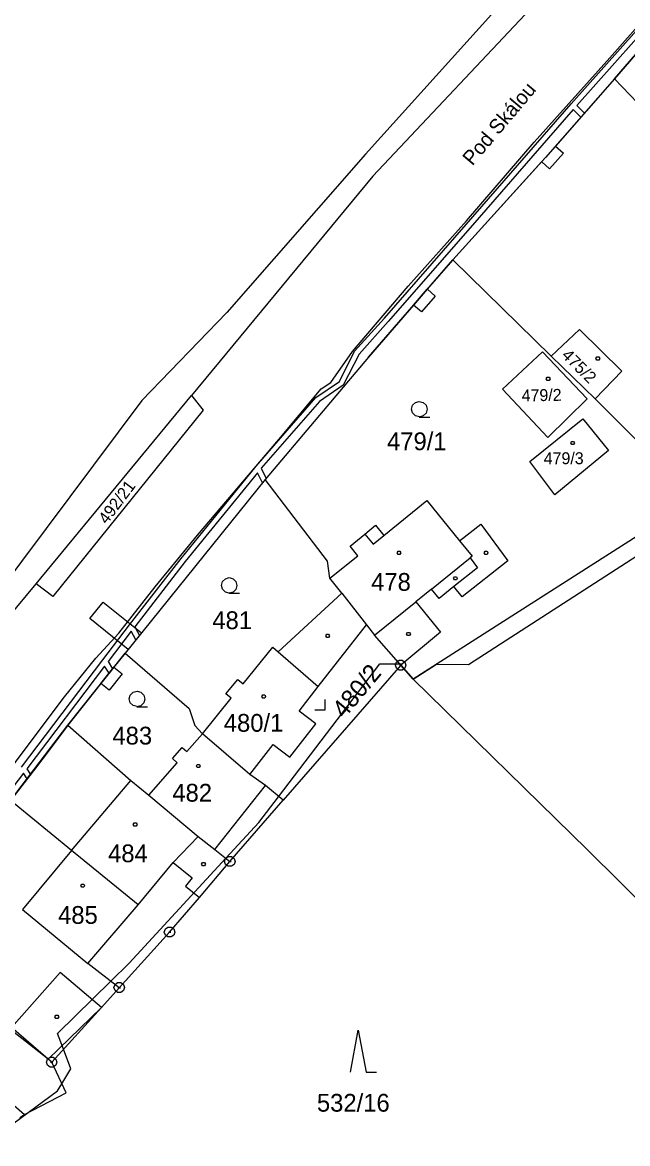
# Model space of a CAD drawing. Extents: x -759699 to -757730, y -1172308 to -1170857.
# Drawn here: x -759493.5 to -759435.7, y -1171818.3 to -1171711.2 of the extents above; entities that cross this region are included whole.
import ezdxf

# ---------------------------------------------------------------- set-up
doc = ezdxf.new("R2010")
doc.units = 0
for name, color, linetype in [('Vrstva 1', 7, 'Continuous'), ('Vrstva 11', 7, 'Continuous'), ('Vrstva 12', 7, 'Continuous'), ('Vrstva 13', 7, 'Continuous'), ('Vrstva 2', 7, 'Continuous'), ('Vrstva 3', 7, 'Continuous'), ('Vrstva 4', 7, 'Continuous'), ('Vrstva 5', 7, 'Continuous'), ('Vrstva 7', 7, 'Continuous'), ('Vrstva 8', 7, 'Continuous')]:
    doc.layers.add(name, color=color, linetype=linetype)

msp = doc.modelspace()

# ---------------------------------------------------------------- linework, layer by layer
at = {"layer": 'Vrstva 1'}
for p, q in [((-759411.06, -1171673.74), (-759460.06, -1171725.87)), ((-759436.98, -1171716.58), (-759431.38, -1171710.06)), ((-759436.98, -1171716.58), (-759443.56, -1171724.07)), ((-759426.3, -1171727.72), (-759436.98, -1171716.58)), ((-759452.43, -1171733.85), (-759443.56, -1171724.07)), ((-759460.06, -1171725.87), (-759477.37, -1171746.83)), ((-759460.46, -1171743.16), (-759452.43, -1171733.85)), ((-759452.43, -1171733.85), (-759443.02, -1171743.06)), ((-759443.02, -1171743.06), (-759440.32, -1171740.54)), ((-759440.32, -1171740.54), (-759436.26, -1171744.52)), ((-759447.66, -1171746.24), (-759443.86, -1171742.67)), ((-759443.86, -1171742.67), (-759439.57, -1171747.14)), ((-759438.83, -1171747.15), (-759443.02, -1171743.06)), ((-759460.46, -1171743.16), (-759470.34, -1171754.86)), ((-759436.26, -1171744.52), (-759438.83, -1171747.15)), ((-759443.33, -1171750.84), (-759447.66, -1171746.24)), ((-759492.23, -1171764.82), (-759477.37, -1171746.83)), ((-759477.37, -1171746.83), (-759476.27, -1171748.22)), ((-759439.57, -1171747.14), (-759443.33, -1171750.84)), ((-759438.83, -1171747.15), (-759429.27, -1171756.73)), ((-759476.27, -1171748.22), (-759490.63, -1171766.05)), ((-759445.05, -1171753.14), (-759439.99, -1171749.05)), ((-759439.99, -1171749.05), (-759437.54, -1171752.08)), ((-759437.54, -1171752.08), (-759442.66, -1171756.31)), ((-759442.66, -1171756.31), (-759445.05, -1171753.14)), ((-759470.34, -1171754.86), (-759483.72, -1171771.46)), ((-759464.38, -1171762.65), (-759470.34, -1171754.86)), ((-759459.01, -1171760.2), (-759454.91, -1171756.88)), ((-759429.27, -1171756.73), (-759456.21, -1171773.94)), ((-759454.91, -1171756.88), (-759451.77, -1171760.72)), ((-759451.77, -1171760.72), (-759449.75, -1171759.13)), ((-759449.75, -1171759.13), (-759447.16, -1171762.64)), ((-759462.24, -1171761.24), (-759460.82, -1171760.07)), ((-759460.82, -1171760.07), (-759459.79, -1171759.24)), ((-759459.79, -1171759.24), (-759459.01, -1171760.2)), ((-759461.5, -1171762.16), (-759462.24, -1171761.24)), ((-759464.16, -1171764.29), (-759461.5, -1171762.16)), ((-759464.16, -1171764.29), (-759464.38, -1171762.65)), ((-759447.16, -1171762.64), (-759451.54, -1171766.07)), ((-759463.03, -1171765.74), (-759464.16, -1171764.29)), ((-759506.59, -1171782.21), (-759492.23, -1171764.82)), ((-759490.63, -1171766.05), (-759492.23, -1171764.82)), ((-759454.45, -1171765.33), (-759455.94, -1171766.54)), ((-759453.73, -1171766.22), (-759454.45, -1171765.33)), ((-759452.32, -1171765.09), (-759453.73, -1171766.22)), ((-759451.54, -1171766.07), (-759452.32, -1171765.09)), ((-759469.12, -1171771.32), (-759463.03, -1171765.74)), ((-759463.03, -1171765.74), (-759460.68, -1171768.74)), ((-759455.94, -1171766.54), (-759453.59, -1171769.46)), ((-759465.28, -1171774.66), (-759460.68, -1171768.74)), ((-759460.68, -1171768.74), (-759459.9, -1171769.74)), ((-759457.4, -1171772.61), (-759459.9, -1171769.74)), ((-759453.59, -1171769.46), (-759457.4, -1171772.61)), ((-759472.45, -1171774.38), (-759469.61, -1171770.89)), ((-759469.61, -1171770.89), (-759469.12, -1171771.32)), ((-759489.2, -1171778.33), (-759483.72, -1171771.46)), ((-759483.72, -1171771.46), (-759477.62, -1171776.75)), ((-759457.4, -1171772.61), (-759468.63, -1171785.52)), ((-759456.21, -1171773.94), (-759457.4, -1171772.61)), ((-759474.1, -1171775.36), (-759472.97, -1171773.97)), ((-759472.97, -1171773.97), (-759472.45, -1171774.38)), ((-759456.21, -1171773.94), (-759439.54, -1171790.25)), ((-759467.09, -1171776.99), (-759465.28, -1171774.66)), ((-759476.34, -1171779.16), (-759473.58, -1171775.77)), ((-759473.58, -1171775.77), (-759474.1, -1171775.36)), ((-759477.62, -1171776.75), (-759477.05, -1171778.38)), ((-759465.51, -1171778.21), (-759467.09, -1171776.99)), ((-759494.67, -1171785.55), (-759489.2, -1171778.33)), ((-759489.2, -1171778.33), (-759483.17, -1171783.63)), ((-759477.05, -1171778.38), (-759476.34, -1171779.16)), ((-759467.99, -1171781.41), (-759465.51, -1171778.21)), ((-759477.82, -1171780.86), (-759476.34, -1171779.16)), ((-759471.81, -1171783.07), (-759476.34, -1171779.16)), ((-759479.21, -1171781.53), (-759478.28, -1171780.46)), ((-759478.28, -1171780.46), (-759477.82, -1171780.86)), ((-759471.81, -1171783.07), (-759469.57, -1171780.19)), ((-759469.57, -1171780.19), (-759467.99, -1171781.41)), ((-759478.75, -1171781.93), (-759479.21, -1171781.53)), ((-759481.47, -1171785.04), (-759478.75, -1171781.93)), ((-759483.17, -1171783.63), (-759481.47, -1171785.04)), ((-759470.31, -1171784.12), (-759471.81, -1171783.07)), ((-759468.63, -1171785.52), (-759470.31, -1171784.12)), ((-759488.86, -1171790.32), (-759494.67, -1171785.55)), ((-759481.47, -1171785.04), (-759476.76, -1171788.98)), ((-759473.71, -1171791.37), (-759468.63, -1171785.52)), ((-759476.76, -1171788.98), (-759475.17, -1171790.21)), ((-759475.17, -1171790.21), (-759473.71, -1171791.37)), ((-759439.54, -1171790.25), (-759416.59, -1171813.09)), ((-759482.48, -1171795.51), (-759488.86, -1171790.32)), ((-759476.63, -1171794.8), (-759473.71, -1171791.37)), ((-759487.29, -1171801.11), (-759482.48, -1171795.51)), ((-759479.47, -1171798.12), (-759476.63, -1171794.8)), ((-759479.47, -1171798.12), (-759484.28, -1171803.43)), ((-759484.28, -1171803.43), (-759487.29, -1171801.11)), ((-759485.98, -1171805.31), (-759484.28, -1171803.43)), ((-759490.74, -1171810.56), (-759485.98, -1171805.31)), ((-759491.08, -1171810.27), (-759494.57, -1171807.25)), ((-759490.74, -1171810.56), (-759491.08, -1171810.27)), ((-759489.36, -1171813.49), (-759490.74, -1171810.56)), ((-759493.35, -1171815.54), (-759489.36, -1171813.49)), ((-759493.78, -1171815.83), (-759493.35, -1171815.54))]:
    msp.add_line(p, q, dxfattribs=at)
at = {"layer": 'Vrstva 11'}
for p, q in [((-759424.03, -1171682.98), (-759460.77, -1171723.76)), ((-759460.77, -1171723.76), (-759474.02, -1171738.9)), ((-759474.02, -1171738.9), (-759482.13, -1171747.3)), ((-759482.13, -1171747.3), (-759506.1, -1171779.29)), ((-759450.91, -1171772.55), (-759429.61, -1171758.75)), ((-759469.08, -1171785.18), (-759459.39, -1171772.48)), ((-759459.39, -1171772.48), (-759457.5, -1171772.49)), ((-759457.5, -1171772.49), (-759457.26, -1171772.49)), ((-759457.26, -1171772.49), (-759457.4, -1171772.61)), ((-759457.4, -1171772.61), (-759456.21, -1171773.94)), ((-759456.21, -1171773.94), (-759453.99, -1171772.52)), ((-759453.99, -1171772.52), (-759450.91, -1171772.55)), ((-759470.95, -1171787.63), (-759469.08, -1171785.18)), ((-759474.11, -1171791.06), (-759470.95, -1171787.63)), ((-759483.34, -1171801.08), (-759474.11, -1171791.06)), ((-759485.09, -1171802.81), (-759483.34, -1171801.08)), ((-759490.17, -1171807.8), (-759485.09, -1171802.81)), ((-759489.61, -1171809.31), (-759490.17, -1171807.8)), ((-759488.92, -1171811.2), (-759489.61, -1171809.31)), ((-759489.78, -1171812.61), (-759488.92, -1171811.2)), ((-759490.2, -1171813.3), (-759489.78, -1171812.61)), ((-759492.98, -1171815.35), (-759490.2, -1171813.3)), ((-759497.02, -1171818.33), (-759492.98, -1171815.35))]:
    msp.add_line(p, q, dxfattribs=at)
at = {"layer": 'Vrstva 12'}
for p, q in [((-759443.02, -1171743.06), (-759440.32, -1171740.54)), ((-759440.32, -1171740.54), (-759436.26, -1171744.52)), ((-759447.66, -1171746.24), (-759443.86, -1171742.67)), ((-759443.86, -1171742.67), (-759439.57, -1171747.14)), ((-759438.83, -1171747.15), (-759443.02, -1171743.06)), ((-759436.26, -1171744.52), (-759438.83, -1171747.15)), ((-759443.33, -1171750.84), (-759447.66, -1171746.24)), ((-759439.57, -1171747.14), (-759443.33, -1171750.84)), ((-759445.05, -1171753.14), (-759439.99, -1171749.05)), ((-759439.99, -1171749.05), (-759437.54, -1171752.08)), ((-759437.54, -1171752.08), (-759442.66, -1171756.31)), ((-759442.66, -1171756.31), (-759445.05, -1171753.14)), ((-759459.01, -1171760.2), (-759454.91, -1171756.88)), ((-759454.91, -1171756.88), (-759451.77, -1171760.72)), ((-759462.24, -1171761.24), (-759460.82, -1171760.07)), ((-759460.82, -1171760.07), (-759460.04, -1171761.03)), ((-759460.04, -1171761.03), (-759459.01, -1171760.2)), ((-759461.5, -1171762.16), (-759462.24, -1171761.24)), ((-759451.77, -1171760.72), (-759450.57, -1171762.19)), ((-759464.16, -1171764.29), (-759461.5, -1171762.16)), ((-759454.45, -1171765.33), (-759450.77, -1171762.35)), ((-759450.57, -1171762.19), (-759450.77, -1171762.35)), ((-759463.03, -1171765.74), (-759464.16, -1171764.29)), ((-759454.45, -1171765.33), (-759455.94, -1171766.54)), ((-759463.03, -1171765.74), (-759460.68, -1171768.74)), ((-759459.9, -1171769.74), (-759455.94, -1171766.54)), ((-759460.68, -1171768.74), (-759459.9, -1171769.74)), ((-759472.45, -1171774.38), (-759469.61, -1171770.89)), ((-759469.61, -1171770.89), (-759469.12, -1171771.32)), ((-759469.12, -1171771.32), (-759465.28, -1171774.66)), ((-759474.1, -1171775.36), (-759472.97, -1171773.97)), ((-759472.97, -1171773.97), (-759472.45, -1171774.38)), ((-759467.09, -1171776.99), (-759465.28, -1171774.66)), ((-759476.34, -1171779.16), (-759473.58, -1171775.77)), ((-759473.58, -1171775.77), (-759474.1, -1171775.36)), ((-759465.51, -1171778.21), (-759467.09, -1171776.99)), ((-759467.99, -1171781.41), (-759465.51, -1171778.21)), ((-759477.82, -1171780.86), (-759476.34, -1171779.16)), ((-759471.81, -1171783.07), (-759476.34, -1171779.16)), ((-759471.81, -1171783.07), (-759476.34, -1171779.16)), ((-759479.21, -1171781.53), (-759478.28, -1171780.46)), ((-759478.28, -1171780.46), (-759477.82, -1171780.86)), ((-759471.81, -1171783.07), (-759469.57, -1171780.19)), ((-759469.57, -1171780.19), (-759467.99, -1171781.41)), ((-759478.75, -1171781.93), (-759479.21, -1171781.53)), ((-759481.47, -1171785.04), (-759478.75, -1171781.93)), ((-759488.86, -1171790.32), (-759483.17, -1171783.63)), ((-759483.17, -1171783.63), (-759481.47, -1171785.04)), ((-759470.31, -1171784.12), (-759471.81, -1171783.07)), ((-759475.17, -1171790.21), (-759470.31, -1171784.12)), ((-759481.47, -1171785.04), (-759476.76, -1171788.98)), ((-759481.47, -1171785.04), (-759476.76, -1171788.98)), ((-759479.15, -1171791.45), (-759476.76, -1171788.98)), ((-759476.76, -1171788.98), (-759475.17, -1171790.21)), ((-759488.86, -1171790.32), (-759493.53, -1171795.95)), ((-759482.48, -1171795.51), (-759488.86, -1171790.32)), ((-759482.48, -1171795.51), (-759488.86, -1171790.32)), ((-759482.48, -1171795.51), (-759479.15, -1171791.45)), ((-759487.29, -1171801.11), (-759482.48, -1171795.51)), ((-759493.53, -1171795.95), (-759487.29, -1171801.11))]:
    msp.add_line(p, q, dxfattribs=at)
at = {"layer": 'Vrstva 13'}
for p, q in [((-759437.42, -1171714.55), (-759429.1, -1171705.11)), ((-759441.11, -1171718.97), (-759432.23, -1171708.97)), ((-759432.02, -1171709.49), (-759440.58, -1171719.13)), ((-759431.38, -1171710.06), (-759436.98, -1171716.58)), ((-759444.65, -1171722.63), (-759437.42, -1171714.55)), ((-759436.98, -1171716.58), (-759442.62, -1171723)), ((-759451.13, -1171730.48), (-759441.11, -1171718.97)), ((-759440.91, -1171719.5), (-759450.76, -1171730.8)), ((-759440.19, -1171720.23), (-759440.91, -1171719.5)), ((-759440.58, -1171719.13), (-759439.85, -1171719.85)), ((-759439.85, -1171719.85), (-759440.19, -1171720.23)), ((-759451.1, -1171730.14), (-759444.65, -1171722.63)), ((-759442.62, -1171723), (-759443.56, -1171724.07)), ((-759443.56, -1171724.07), (-759442.62, -1171723)), ((-759441.86, -1171723.67), (-759443.18, -1171725.17)), ((-759442.62, -1171723), (-759442.6, -1171723.01)), ((-759442.6, -1171723.01), (-759441.86, -1171723.67)), ((-759443.94, -1171724.49), (-759452.43, -1171733.85)), ((-759443.56, -1171724.07), (-759443.94, -1171724.49)), ((-759443.94, -1171724.49), (-759443.56, -1171724.07)), ((-759443.93, -1171724.5), (-759443.94, -1171724.49)), ((-759443.18, -1171725.17), (-759443.93, -1171724.5)), ((-759456.67, -1171736.39), (-759451.1, -1171730.14)), ((-759458.95, -1171739.43), (-759451.13, -1171730.48)), ((-759450.76, -1171730.8), (-759458.58, -1171739.76)), ((-759452.43, -1171733.85), (-759454.86, -1171736.67)), ((-759462, -1171742.64), (-759456.67, -1171736.39)), ((-759454.86, -1171736.67), (-759456.16, -1171738.19)), ((-759456.16, -1171738.19), (-759454.86, -1171736.67)), ((-759454.86, -1171736.67), (-759454.85, -1171736.68)), ((-759454.85, -1171736.68), (-759454.1, -1171737.33)), ((-759454.1, -1171737.33), (-759455.41, -1171738.85)), ((-759456.16, -1171738.19), (-759460.46, -1171743.16)), ((-759455.41, -1171738.85), (-759456.16, -1171738.19)), ((-759461.8, -1171742.6), (-759458.95, -1171739.43)), ((-759458.58, -1171739.76), (-759461.38, -1171742.88)), ((-759464.06, -1171745.6), (-759462, -1171742.64)), ((-759463.26, -1171745.5), (-759461.8, -1171742.6)), ((-759461.38, -1171742.88), (-759462.88, -1171745.84)), ((-759460.46, -1171743.16), (-759470.34, -1171754.86)), ((-759469.04, -1171751.04), (-759465, -1171746.21)), ((-759465.49, -1171747.01), (-759463.26, -1171745.5)), ((-759462.88, -1171745.84), (-759465.15, -1171747.39)), ((-759465, -1171746.21), (-759464.06, -1171745.6)), ((-759471.21, -1171753.59), (-759465.49, -1171747.01)), ((-759465.15, -1171747.39), (-759470.72, -1171753.79)), ((-759476.82, -1171760.17), (-759469.04, -1171751.04)), ((-759472.59, -1171755.27), (-759471.21, -1171753.59)), ((-759470.72, -1171753.79), (-759470.25, -1171754.75)), ((-759470.34, -1171754.86), (-759483.72, -1171771.46)), ((-759471.07, -1171754.21), (-759472.2, -1171755.59)), ((-759470.6, -1171755.18), (-759471.07, -1171754.21)), ((-759470.34, -1171754.86), (-759470.6, -1171755.18)), ((-759470.25, -1171754.75), (-759470.34, -1171754.86)), ((-759478.38, -1171762.4), (-759472.59, -1171755.27)), ((-759472.2, -1171755.59), (-759477.99, -1171762.71)), ((-759480.87, -1171765.13), (-759476.82, -1171760.17)), ((-759483.3, -1171768.76), (-759478.38, -1171762.4)), ((-759477.99, -1171762.71), (-759482.8, -1171768.94)), ((-759484.33, -1171769.56), (-759480.87, -1171765.13)), ((-759487.09, -1171768.15), (-759485.82, -1171766.58)), ((-759485.82, -1171766.58), (-759482.16, -1171769.53)), ((-759483.43, -1171771.1), (-759487.09, -1171768.15)), ((-759485.86, -1171772.1), (-759483.3, -1171768.76)), ((-759486.52, -1171771.93), (-759484.33, -1171769.56)), ((-759483.14, -1171769.37), (-759485.36, -1171772.27)), ((-759482.16, -1171769.53), (-759483.43, -1171771.1)), ((-759482.71, -1171770.2), (-759483.14, -1171769.37)), ((-759482.8, -1171768.94), (-759482.36, -1171769.78)), ((-759482.36, -1171769.78), (-759482.71, -1171770.2)), ((-759489.53, -1171775.62), (-759486.52, -1171771.93)), ((-759483.72, -1171771.46), (-759484.79, -1171772.81)), ((-759493.63, -1171782.34), (-759485.86, -1171772.1)), ((-759485.68, -1171772.69), (-759493.12, -1171782.51)), ((-759484.79, -1171772.81), (-759486.03, -1171774.37)), ((-759486.03, -1171774.37), (-759484.79, -1171772.81)), ((-759485.25, -1171773.38), (-759485.68, -1171772.69)), ((-759485.36, -1171772.27), (-759484.92, -1171772.97)), ((-759484.92, -1171772.97), (-759485.25, -1171773.38)), ((-759484.79, -1171772.81), (-759484, -1171773.43)), ((-759484, -1171773.43), (-759485.25, -1171775)), ((-759486.03, -1171774.37), (-759489.2, -1171778.33)), ((-759485.25, -1171775), (-759486.03, -1171774.37)), ((-759493.18, -1171780.51), (-759489.53, -1171775.62)), ((-759489.2, -1171778.33), (-759491.09, -1171780.85)), ((-759497.62, -1171786.39), (-759493.18, -1171780.51)), ((-759491.09, -1171780.85), (-759492.3, -1171782.45)), ((-759492.3, -1171782.45), (-759494.67, -1171785.55)), ((-759493.12, -1171782.51), (-759492.77, -1171783.04)), ((-759493.44, -1171782.93), (-759495.37, -1171785.47)), ((-759493.09, -1171783.47), (-759493.44, -1171782.93)), ((-759492.77, -1171783.04), (-759493.09, -1171783.47))]:
    msp.add_line(p, q, dxfattribs=at)
at = {"layer": 'Vrstva 3'}
for points in [[(-759455.61, -1171748.87), (-759455.99, -1171748.77), (-759456.26, -1171748.5), (-759456.36, -1171748.13), (-759456.26, -1171747.76), (-759455.99, -1171747.49), (-759455.62, -1171747.39), (-759455.25, -1171747.49), (-759454.98, -1171747.76), (-759454.88, -1171748.14), (-759454.98, -1171748.52), (-759455.25, -1171748.79), (-759455.63, -1171748.89), (-759454.63, -1171748.89)], [(-759473.77, -1171765.72), (-759474.15, -1171765.62), (-759474.42, -1171765.35), (-759474.52, -1171764.98), (-759474.42, -1171764.61), (-759474.15, -1171764.34), (-759473.78, -1171764.24), (-759473.41, -1171764.34), (-759473.14, -1171764.61), (-759473.04, -1171764.99), (-759473.14, -1171765.37), (-759473.41, -1171765.64), (-759473.79, -1171765.74), (-759472.79, -1171765.74)], [(-759482.58, -1171776.57), (-759482.96, -1171776.47), (-759483.23, -1171776.2), (-759483.33, -1171775.83), (-759483.23, -1171775.46), (-759482.96, -1171775.19), (-759482.59, -1171775.09), (-759482.22, -1171775.19), (-759481.95, -1171775.46), (-759481.85, -1171775.84), (-759481.95, -1171776.22), (-759482.22, -1171776.49), (-759482.6, -1171776.59), (-759481.6, -1171776.59)], [(-759465.61, -1171776.88), (-759464.61, -1171776.88), (-759464.61, -1171775.88)], [(-759462.2, -1171811.5), (-759461.45, -1171807.5), (-759460.7, -1171811.5), (-759459.7, -1171811.5)]]:
    msp.add_lwpolyline(points, dxfattribs=at)
at = {"layer": 'Vrstva 4'}
for p, q in [((-759460.82, -1171760.07), (-759460.04, -1171761.03)), ((-759460.04, -1171761.03), (-759459.01, -1171760.2)), ((-759451.77, -1171760.72), (-759450.57, -1171762.19)), ((-759454.45, -1171765.33), (-759450.77, -1171762.35)), ((-759450.57, -1171762.19), (-759450.77, -1171762.35)), ((-759450.77, -1171762.35), (-759450.06, -1171763.29)), ((-759450.06, -1171763.29), (-759452.32, -1171765.09)), ((-759459.9, -1171769.74), (-759455.94, -1171766.54)), ((-759469.12, -1171771.32), (-759465.28, -1171774.66)), ((-759488.86, -1171790.32), (-759483.17, -1171783.63)), ((-759475.17, -1171790.21), (-759470.31, -1171784.12)), ((-759479.15, -1171791.45), (-759476.76, -1171788.98)), ((-759488.86, -1171790.32), (-759493.53, -1171795.95)), ((-759482.48, -1171795.51), (-759479.15, -1171791.45)), ((-759479.15, -1171791.45), (-759477.33, -1171792.93)), ((-759477.33, -1171792.93), (-759477.97, -1171793.72)), ((-759477.97, -1171793.72), (-759476.63, -1171794.8)), ((-759493.53, -1171795.95), (-759487.29, -1171801.11)), ((-759489.93, -1171801.99), (-759494.57, -1171807.25)), ((-759485.98, -1171805.31), (-759489.93, -1171801.99)), ((-759491.08, -1171810.27), (-759485.98, -1171805.31)), ((-759491.08, -1171810.27), (-759495.36, -1171806.9)), ((-759499.07, -1171810.57), (-759493.35, -1171815.54))]:
    msp.add_line(p, q, dxfattribs=at)
at = {"layer": 'Vrstva 5'}
for points in [[(-759438.48, -1171743.14), (-759438.39, -1171743.29), (-759438.48, -1171743.44), (-759438.66, -1171743.44), (-759438.75, -1171743.29), (-759438.66, -1171743.14)], [(-759443.22, -1171745.09), (-759443.13, -1171745.24), (-759443.22, -1171745.39), (-759443.4, -1171745.39), (-759443.49, -1171745.24), (-759443.4, -1171745.09)], [(-759440.88, -1171751.22), (-759440.79, -1171751.37), (-759440.88, -1171751.52), (-759441.06, -1171751.52), (-759441.15, -1171751.37), (-759441.06, -1171751.22)], [(-759457.47, -1171761.72), (-759457.38, -1171761.87), (-759457.47, -1171762.02), (-759457.65, -1171762.02), (-759457.74, -1171761.87), (-759457.65, -1171761.72)], [(-759449.15, -1171761.72), (-759449.06, -1171761.87), (-759449.15, -1171762.02), (-759449.33, -1171762.02), (-759449.42, -1171761.87), (-759449.33, -1171761.72)], [(-759452.08, -1171764.15), (-759451.99, -1171764.3), (-759452.08, -1171764.45), (-759452.26, -1171764.45), (-759452.35, -1171764.3), (-759452.26, -1171764.15)], [(-759464.29, -1171769.65), (-759464.2, -1171769.8), (-759464.29, -1171769.95), (-759464.47, -1171769.95), (-759464.56, -1171769.8), (-759464.47, -1171769.65)], [(-759456.56, -1171769.47), (-759456.47, -1171769.62), (-759456.56, -1171769.77), (-759456.74, -1171769.77), (-759456.83, -1171769.62), (-759456.74, -1171769.47)], [(-759470.39, -1171775.45), (-759470.3, -1171775.6), (-759470.39, -1171775.75), (-759470.57, -1171775.75), (-759470.66, -1171775.6), (-759470.57, -1171775.45)], [(-759476.65, -1171782.09), (-759476.56, -1171782.24), (-759476.65, -1171782.39), (-759476.83, -1171782.39), (-759476.92, -1171782.24), (-759476.83, -1171782.09)], [(-759482.68, -1171787.69), (-759482.59, -1171787.84), (-759482.68, -1171787.99), (-759482.86, -1171787.99), (-759482.95, -1171787.84), (-759482.86, -1171787.69)], [(-759476.15, -1171791.48), (-759476.06, -1171791.63), (-759476.15, -1171791.78), (-759476.33, -1171791.78), (-759476.42, -1171791.63), (-759476.33, -1171791.48)], [(-759487.68, -1171793.53), (-759487.59, -1171793.68), (-759487.68, -1171793.83), (-759487.86, -1171793.83), (-759487.95, -1171793.68), (-759487.86, -1171793.53)], [(-759490.16, -1171806.07), (-759490.07, -1171806.22), (-759490.16, -1171806.37), (-759490.34, -1171806.37), (-759490.43, -1171806.22), (-759490.34, -1171806.07)]]:
    msp.add_lwpolyline(points, close=True, dxfattribs=at)
at = {"layer": 'Vrstva 8'}
for p, q in [((-759457.52, -1171772.61), (-759457.28, -1171772.61)), ((-759473.83, -1171791.37), (-759473.59, -1171791.37)), ((-759479.59, -1171798.12), (-759479.35, -1171798.12)), ((-759484.4, -1171803.43), (-759484.16, -1171803.43)), ((-759490.86, -1171810.56), (-759490.62, -1171810.56))]:
    msp.add_line(p, q, dxfattribs=at)
for points in [[(-759457.25, -1171772.13), (-759457, -1171772.31), (-759456.9, -1171772.6), (-759457, -1171772.89), (-759457.25, -1171773.07), (-759457.56, -1171773.07), (-759457.81, -1171772.89), (-759457.91, -1171772.6), (-759457.81, -1171772.31), (-759457.56, -1171772.13)], [(-759473.56, -1171790.89), (-759473.31, -1171791.07), (-759473.21, -1171791.36), (-759473.31, -1171791.65), (-759473.56, -1171791.83), (-759473.87, -1171791.83), (-759474.12, -1171791.65), (-759474.22, -1171791.36), (-759474.12, -1171791.07), (-759473.87, -1171790.89)], [(-759479.32, -1171797.64), (-759479.07, -1171797.82), (-759478.97, -1171798.11), (-759479.07, -1171798.4), (-759479.32, -1171798.58), (-759479.63, -1171798.58), (-759479.88, -1171798.4), (-759479.98, -1171798.11), (-759479.88, -1171797.82), (-759479.63, -1171797.64)], [(-759484.13, -1171802.95), (-759483.88, -1171803.13), (-759483.78, -1171803.42), (-759483.88, -1171803.71), (-759484.13, -1171803.89), (-759484.44, -1171803.89), (-759484.69, -1171803.71), (-759484.79, -1171803.42), (-759484.69, -1171803.13), (-759484.44, -1171802.95)], [(-759490.59, -1171810.08), (-759490.34, -1171810.26), (-759490.24, -1171810.55), (-759490.34, -1171810.84), (-759490.59, -1171811.02), (-759490.9, -1171811.02), (-759491.15, -1171810.84), (-759491.25, -1171810.55), (-759491.15, -1171810.26), (-759490.9, -1171810.08)]]:
    msp.add_lwpolyline(points, close=True, dxfattribs=at)

# ---------------------------------------------------------------- texts
at = {"layer": 'Vrstva 2'}
for s, height, rotation, p in [('475/2', 1.14, 315.01219, (-759442.096, -1171743.074)), ('479/2', 1.14, 0.91673, (-759445.834, -1171747.397)), ('492/21', 1.14, 52.9986, (-759485.473, -1171759.21)), ('480/2', 1.7, 50.1911, (-759462.789, -1171777.785))]:
    msp.add_text(s, height=height, rotation=rotation, dxfattribs=at).set_placement(p)
for s, height, p in [('479/1', 1.7, (-759458.705, -1171752.06)), ('479/3', 1.14, (-759443.734, -1171753.4)), ('478', 1.7, (-759460.224, -1171765.5)), ('481', 1.7, (-759475.393, -1171769.16)), ('480/1', 1.7, (-759474.299, -1171778.97)), ('483', 1.7, (-759484.938, -1171780.19)), ('482', 1.7, (-759479.215, -1171785.65)), ('484', 1.7, (-759485.351, -1171791.44)), ('485', 1.7, (-759490.128, -1171797.33)), ('532/16', 1.7, (-759465.402, -1171815.28))]:
    msp.add_text(s, height=height, dxfattribs=at).set_placement(p)
at = {"layer": 'Vrstva 7'}
msp.add_text('Pod Skálou', height=1.4, rotation=49.84733, dxfattribs=at).set_placement((-759450.55, -1171724.947))

doc.saveas('drawing.dxf')
